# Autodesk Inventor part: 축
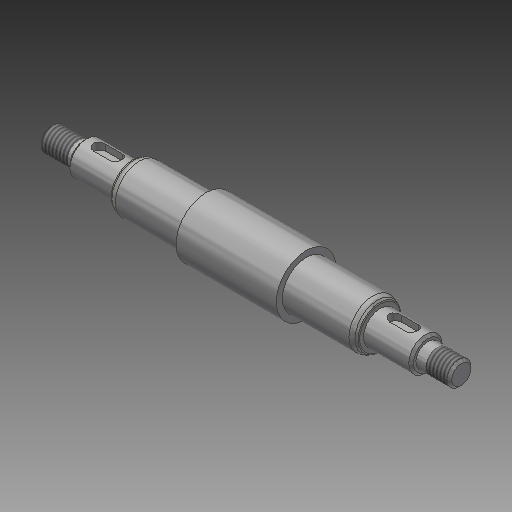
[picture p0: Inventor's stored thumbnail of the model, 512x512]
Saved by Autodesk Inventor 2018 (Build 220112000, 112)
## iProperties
Created: 2020-05
Part Number: 축
Material: 강철, 연강
Document SubType Name: Modeling
Designer: mduedu
Density: 1 g/cm^3
Appearance: 강철
Author: mduedu
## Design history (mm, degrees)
sketch "스케치1"
  geometry: L1 (0, 0)-(21, 0); L2 (21, 0)-(21, 12.5); L3 (21, 12.5)-(0, 12.5); L4 (0, 12.5)-(0, 0); L5 (21, 0)-(52, 0); L6 (52, 0)-(52, 10); L7 (52, 10)-(21, 10); L8 (21, 10)-(21, 0); L9 (52, 0)-(72, 0); L10 (72, 0)-(72, 7); L11 (72, 7)-(52, 7); L12 (52, 7)-(52, 0); L13 (72, 0)-(86, 0); L14 (86, 0)-(86, 5); L15 (86, 5)-(72, 5); L16 (72, 5)-(72, 0); L17 (0, 0)-(-21, 0); L18 (-21, 0)-(-21, 12.5); L19 (-21, 12.5)-(0, 12.5); L20 (-21, 0)-(-52, 0); L21 (-52, 0)-(-52, 10); L22 (-52, 10)-(-21, 10); L23 (-21, 10)-(-21, 0); L24 (-52, 0)-(-72, 0); L25 (-72, 0)-(-72, 7); L26 (-72, 7)-(-52, 7); L27 (-52, 7)-(-52, 0); L28 (-72, 0)-(-86, 0); L29 (-86, 0)-(-86, 5); L30 (-86, 5)-(-72, 5); L31 (-72, 5)-(-72, 0)
  constraints: 62 end point, 11 symmetric about line, 8 parallel, 4 horizontal, 4 perpendicular
  dimensions: "d0" = 172 distance between parallel lines of L14 L29; "d2" = 25 diameter of L3 L1; "d3" = 20 diameter of L7 L5; "d4" = 14 diameter of L11 L9; "d5" = 10 diameter of L15 L13; "d6" = 42 distance of L2.end L18.end; "d7" = 31 distance of L6.end L7.end; "d8" = 20 distance of L10.end L11.end; "d9" = 14 distance of L14.end L15.end (derived)
revolve "회전1" sketch "스케치1" stored, may be unused: angle "d10" = 90 deg
sketch "스케치2"
  geometry: L1 (72, -5)-(72, -7) reference; L2 (72, -7)-(52, -7) reference; L3 (52, -7)-(52, -10) reference; L4 (52, -10)-(21, -10) reference; L5 (21, -10)-(21, -12.5) reference; L6 (21, -12.5)-(-21, -12.5) reference; L7 (-21, -12.5)-(-21, -10) reference; L8 (-21, -10)-(-52, -10) reference; L9 (-52, -10)-(-52, -7) reference; L10 (-52, -7)-(-72, -7) reference; L11 (-72, -7)-(-72, -5) reference; L12 (-72, -5)-(-86, -5) reference; L13 (-86, -5)-(-86, 5) reference; L14 (-86, 5)-(-72, 5) reference; L15 (-72, 5)-(-72, 7) reference; L16 (-72, 7)-(-52, 7) reference; L17 (-52, 7)-(-52, 10) reference; L18 (-52, 10)-(-21, 10) reference; L19 (-21, 10)-(-21, 12.5) reference; L20 (-21, 12.5)-(21, 12.5) reference; L21 (21, 12.5)-(21, 10) reference; L22 (21, 10)-(52, 10) reference; L23 (52, 10)-(52, 7) reference; L24 (52, 7)-(72, 7) reference; L25 (72, 7)-(72, 5) reference; L26 (72, 5)-(86, 5) reference; L27 (86, 5)-(86, -5) reference; L28 (86, -5)-(72, -5) reference; L29 (-86, 0)-(86, 0); L30 (0, -12.5)-(0, 12.5); L31 (-52, 8.85)-(-50.008, 10); L32 (-50.008, 10)-(-52, 10); L33 (-52, 10)-(-52, 8.85); 1 further point
  constraints: 10 end point, 4 midpoint, 2 collinear, 2 point on line
  dimensions: "d11" = 17.7 diameter of L31.start L29; "d12" = 30 deg angle of L31 L32
revolve "회전2" sketch "스케치2" stored, may be unused: angle "d13" = 90 deg
fillet "모깎기1" dims "d14" = 4, "d15" = 0.5
node "작업 평면1"
sketch "스케치3"
  geometry: L1 (-6, 2.5)-(6, 2.5); L2 (6, 2.5)-(6, -2.5); L3 (6, -2.5)-(-6, -2.5); L4 (-6, -2.5)-(-6, 2.5); L5 (-10, 8.561)-(-10, -8.561) reference; 2 further points
  constraints: 8 end point, 2 parallel, 1 horizontal, 1 horizontal alignment, 1 midpoint, 1 perpendicular
  dimensions: "d16" = 5 distance of L1.end L2.end; "d18" = 4 distance between parallel lines of L4 L5; "d19" = 12 distance of L1.start L1.end
extrude "돌출1" cut sketch "스케치3" distance "d20" = 3; taper "d21" = 0 deg
fillet "모깎기2" dims "d22" = 2.5
fillet "모깎기3" dims "d23" = 2.5
feature "스레드1" dims "d24" = 12, "d25" = 0
feature "스레드2" dims "d26" = 10, "d27" = 0
chamfer "모따기1" distance "d28" = 1; stored, may be unused: second distance "d29" = 2, angle "d30" = 45 deg
chamfer "모따기2" distance "d31" = 1; stored, may be unused: second distance "d32" = 2, angle "d33" = 45 deg
node "솔리드1"
mirror "대칭1"
mirror "대칭2"
node "절단 모서리 투영1"
